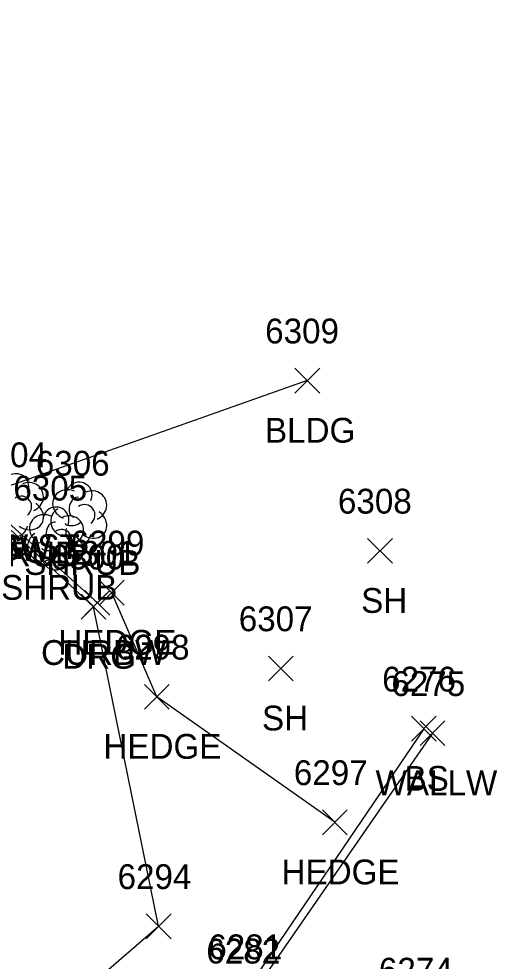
# Model space of a CAD drawing. Extents: x 1769141 to 1770817, y 735471 to 742405.
# Drawn here: x 1770355.8 to 1770394.4, y 740558.9 to 740634.9 of the extents above; entities that cross this region are included whole.
import ezdxf

# ---------------------------------------------------------------- set-up
doc = ezdxf.new("R2010")
doc.units = 0
for name, color, linetype in [('L_A', 7, 'Continuous'), ('L_I', 7, 'Continuous'), ('L_TIC', 7, 'Continuous'), ('LAHR', 7, 'Continuous'), ('LBC', 7, 'Continuous'), ('LELB', 7, 'Continuous'), ('LSH', 7, 'Continuous'), ('LW', 7, 'Continuous'), ('R_A', 7, 'Continuous'), ('R_I', 7, 'Continuous'), ('R_TIC', 7, 'Continuous'), ('RC', 7, 'Continuous'), ('RDG', 7, 'Continuous')]:
    doc.layers.add(name, color=color, linetype=linetype)

msp = doc.modelspace()

# ---------------------------------------------------------------- linework, layer by layer
at = {"layer": 'L_TIC'}
for points in [[(1770378.068, 740604.704), (1770380.068, 740606.704)], [(1770380.068, 740604.704), (1770378.068, 740606.704)], [(1770383.924, 740590.989), (1770385.924, 740592.989)], [(1770385.924, 740590.989), (1770383.924, 740592.989)], [(1770362.306, 740587.613), (1770364.306, 740589.613)], [(1770364.306, 740587.613), (1770362.306, 740589.613)], [(1770375.932, 740581.509), (1770377.932, 740583.509)], [(1770377.932, 740581.509), (1770375.932, 740583.509)], [(1770365.938, 740579.226), (1770367.938, 740581.226)], [(1770367.938, 740579.226), (1770365.938, 740581.226)], [(1770387.464, 740576.649), (1770389.464, 740578.649)], [(1770389.464, 740576.649), (1770387.464, 740578.649)], [(1770388.154, 740576.288), (1770390.154, 740578.288)], [(1770390.154, 740576.288), (1770388.154, 740578.288)], [(1770380.293, 740569.108), (1770382.293, 740571.108)], [(1770382.293, 740569.108), (1770380.293, 740571.108)]]:
    msp.add_lwpolyline(points, dxfattribs=at)
at = {"layer": 'LAHR'}
msp.add_lwpolyline([(1770381.293, 740570.108), (1770366.938, 740580.226), (1770363.306, 740588.613)], dxfattribs=at)
at = {"layer": 'LBC'}
msp.add_lwpolyline([(1770379.068, 740605.704), (1770352.318, 740596.262), (1770352.112, 740596.326), (1770340.803, 740628.648), (1770332.856, 740651.566), (1770359.461, 740660.913)], dxfattribs=at)
at = {"layer": 'LELB'}
msp.add_lwpolyline([(1770388.464, 740577.649), (1770373.832, 740556.07), (1770359.907, 740536.134), (1770336.656, 740531.325)], dxfattribs=at)
at = {"layer": 'LSH'}
for p, q in [((1770360.633, 740595.048), (1770360.633, 740595.048)), ((1770360.633, 740595.048), (1770360.633, 740595.048)), ((1770358.769, 740593.039), (1770358.769, 740593.039)), ((1770358.769, 740593.039), (1770358.769, 740593.039))]:
    msp.add_line(p, q, dxfattribs=at)
for centre in [(1770355.577, 740597.159), (1770360.679, 740596.481), (1770358.816, 740594.473)]:
    msp.add_arc(centre, 1.047, 335.52715, 180.95627, dxfattribs=at)
for centre, major_axis, ratio, start_param, end_param in [((1770356.571, 740596.309), (-1.141, -0.483), 0.949671, 1.570796, 4.712389), ((1770359.841, 740595.714), (1.21, -0.512), 0.895232, 1.570796, 4.712389), ((1770361.674, 740595.631), (-1.141, -0.483), 0.949671, 1.570796, 4.712389), ((1770356.03, 740595.559), (-0.5, 0.667), 0.989748, 3.141593, 6.283185), ((1770360.424, 740595.506), (-0.208, -0.792), 0.645439, 3.141593, 6.283185), ((1770356.53, 740594.892), (-1.09, 0.792), 0.841452, 1.570796, 4.712389), ((1770359.549, 740594.339), (0.584, -1.042), 0.959034, 3.141593, 6.283185), ((1770361.133, 740594.881), (-0.5, 0.667), 0.989748, 3.141593, 6.283185), ((1770357.977, 740593.705), (1.21, -0.512), 0.895232, 1.570796, 4.712389), ((1770359.81, 740593.622), (-1.141, -0.483), 0.949671, 1.570796, 4.712389), ((1770361.633, 740594.214), (-1.09, 0.792), 0.841452, 1.570796, 4.712389), ((1770355.53, 740594.225), (0.265, 1.061), 0.942809, 1.570796, 4.712389), ((1770358.56, 740593.497), (-0.208, -0.792), 0.645439, 3.141593, 6.283185), ((1770359.269, 740592.872), (-0.5, 0.667), 0.989748, 3.141593, 6.283185), ((1770360.633, 740593.548), (0.265, 1.061), 0.942809, 1.570796, 4.712389), ((1770360.174, 740594.297), (-0.625, -0.083), 0.423636, 0, 3.141593), ((1770357.686, 740592.33), (0.584, -1.042), 0.959034, 3.141593, 6.283185), ((1770359.769, 740592.206), (-1.09, 0.792), 0.841452, 1.570796, 4.712389), ((1770358.311, 740592.289), (-0.625, -0.083), 0.423636, 0, 3.141593), ((1770358.769, 740591.539), (0.265, 1.061), 0.942809, 1.570796, 4.712389)]:
    msp.add_ellipse(centre, major_axis=major_axis, ratio=ratio, start_param=start_param, end_param=end_param, dxfattribs=at)
at = {"layer": 'LW'}
msp.add_lwpolyline([(1770389.154, 740577.288), (1770374.242, 740555.726), (1770360.27, 740535.741), (1770355.037, 740525.68)], dxfattribs=at)
at = {"layer": 'R_TIC'}
for points in [[(1770360.841, 740586.482), (1770362.841, 740588.482)], [(1770362.841, 740586.482), (1770360.841, 740588.482)], [(1770361.15, 740586.791), (1770363.15, 740588.791)], [(1770363.15, 740586.791), (1770361.15, 740588.791)], [(1770366.088, 740560.728), (1770368.088, 740562.728)], [(1770368.088, 740560.728), (1770366.088, 740562.728)]]:
    msp.add_lwpolyline(points, dxfattribs=at)
at = {"layer": 'RC'}
msp.add_lwpolyline([(1770362.15, 740587.791), (1770352.844, 740596.162)], dxfattribs=at)
at = {"layer": 'RDG'}
msp.add_lwpolyline([(1770336.339, 740537.078), (1770351.837, 740548.575), (1770367.088, 740561.728), (1770361.841, 740587.482), (1770352.445, 740596.17)], dxfattribs=at)

# ---------------------------------------------------------------- texts
at = {"layer": 'L_A'}
for s, p in [('BLDG', (1770375.659, 740600.704)), ('BLDG STPW ST', (1770340.828, 740591.326)), ('BLDG', (1770348.909, 740591.262)), ('SHRUB', (1770351.16, 740590.725)), ('SHRUB', (1770356.263, 740590.048)), ('SHRUB', (1770354.399, 740588.039)), ('SH', (1770383.412, 740586.989)), ('HEDGE', (1770359.007, 740583.613)), ('SH', (1770375.42, 740577.509)), ('HEDGE', (1770362.639, 740575.226)), ('WALLW', (1770384.572, 740572.288)), ('BS', (1770386.905, 740572.649)), ('HEDGE', (1770376.994, 740565.108))]:
    msp.add_text(s, height=2, dxfattribs=at).set_placement(p)
at = {"layer": 'L_I'}
for s, p in [('6309', (1770375.675, 740608.704)), ('6304', (1770352.144, 740598.725)), ('6306', (1770357.192, 740598.048)), ('6305', (1770355.383, 740596.039)), ('6308', (1770381.538, 740594.989)), ('6299', (1770359.991, 740591.613)), ('6307', (1770373.546, 740585.509)), ('6298', (1770363.631, 740583.226)), ('6276', (1770385.102, 740580.649)), ('6275', (1770385.847, 740580.288)), ('6297', (1770377.986, 740573.108)), ('6281', (1770371.092, 740559.07)), ('6282', (1770370.935, 740558.726)), ('6274', (1770384.839, 740557.187))]:
    msp.add_text(s, height=2, dxfattribs=at).set_placement(p)
at = {"layer": 'R_A'}
for s, p in [('CURBW', (1770348.309, 740591.162)), ('CURBW', (1770357.615, 740582.791)), ('DRG', (1770359.329, 740582.482))]:
    msp.add_text(s, height=2, dxfattribs=at).set_placement(p)
at = {"layer": 'R_I'}
for s, p in [('6300', (1770358.368, 740590.482)), ('6301', (1770359.332, 740590.791)), ('6294', (1770363.781, 740564.728))]:
    msp.add_text(s, height=2, dxfattribs=at).set_placement(p)

doc.saveas('drawing.dxf')
